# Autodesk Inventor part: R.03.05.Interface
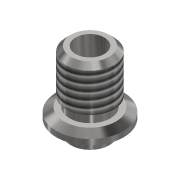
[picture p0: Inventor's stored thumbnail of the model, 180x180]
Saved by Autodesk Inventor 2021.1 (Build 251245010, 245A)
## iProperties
Created: 2021-02
Part Number: R.03.05.Interface
Material: Stainless Steel
Document SubType Name: Modeling
Designer: Михальчик
Density: 8 g/cm^3
Appearance: Semi-Polished
Author: Михальчик
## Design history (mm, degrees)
sketch "Sketch1"
  geometry: L1 (0, 0)-(0, 26.913); L2 (0, 0)-(4, 0); L3 (4, 0)-(4, 2); L4 (4, 2)-(0, 2); L5 (0, 2)-(0, 0); L6 (0, 2)-(7, 2); L7 (7, 2)-(7, 5); L8 (7, 5)-(0, 5); L9 (0, 5)-(0, 2); L10 (0, 5)-(4.25, 5); L11 (4.25, 5)-(4.25, 7); L12 (4.25, 7)-(0, 7); L13 (0, 7)-(0, 5); L14 (0, 7)-(5, 7); L15 (5, 7)-(5, 16); L16 (5, 16)-(0, 16); L17 (0, 16)-(0, 7); L18 (0, 0)-(3, 0); L19 (3, 0)-(3, 16); L20 (3, 16)-(0, 16); L21 (0, 16)-(0, 0); L22 (5.4, 5)-(7, 4.076); L23 (5.4, 5)-(7.248, 5); L24 (7, 2.924)-(5.4, 2); 4 further points
  constraints: 48 end point, 10 parallel, 6 horizontal, 5 perpendicular, 5 point on line, 2 equal length, 1 vertical
  dimensions: "d0" = 4 distance of L4.end L3.end; "d1" = 2 distance of L3.end L2.end; "d2" = 7 distance of L8.end L7.end; "d3" = 3 distance of L7.end L6.end; "d4" = 4.25 distance of L12.end L11.end; "d5" = 16 distance between parallel lines of L2 L16; "d6" = 5 distance of L15.end L16.end; "d7" = 3 distance of L20.end L19.end; "d8" = 2 distance of L10.end L11.end; "d9" = 30 deg angle of L22 L23; "d10" = 30 deg angle of L6 L24; "d11" = 1.6 horizontal distance of L22.start L22.end
revolve "Revolution1" sketch "Sketch1" stored, may be unused: angle "d12" = 90 deg
chamfer "Chamfer1" distance "d13" = 1; stored, may be unused: second distance "d14" = 2, angle "d15" = 45 deg
thread "Thread1" dims "d16" = 8, "d17" = 0
sketch "Sketch2"
  geometry: L1 (0, -6.928)-(-6, -3.464); L2 (-6, -3.464)-(-6, 3.464); L3 (-6, 3.464)-(0, 6.928); L4 (0, 6.928)-(6, 3.464); L5 (6, 3.464)-(6, -3.464); L6 (6, -3.464)-(0, -6.928); C1 r 7 at (0, 0); C2 r 7 at (0, 0) reference; 2 further points
  constraints: 12 end point, 2 coincident, 1 centre point, 1 concentric, 1 vertical, 13 other
  dimensions: "d18" = 12 distance between parallel lines of L2 L5
extrude "Extrusion1" cut sketch "Sketch2" distance "d19" = 10; taper "d20" = 0 deg
body "Solid1"
